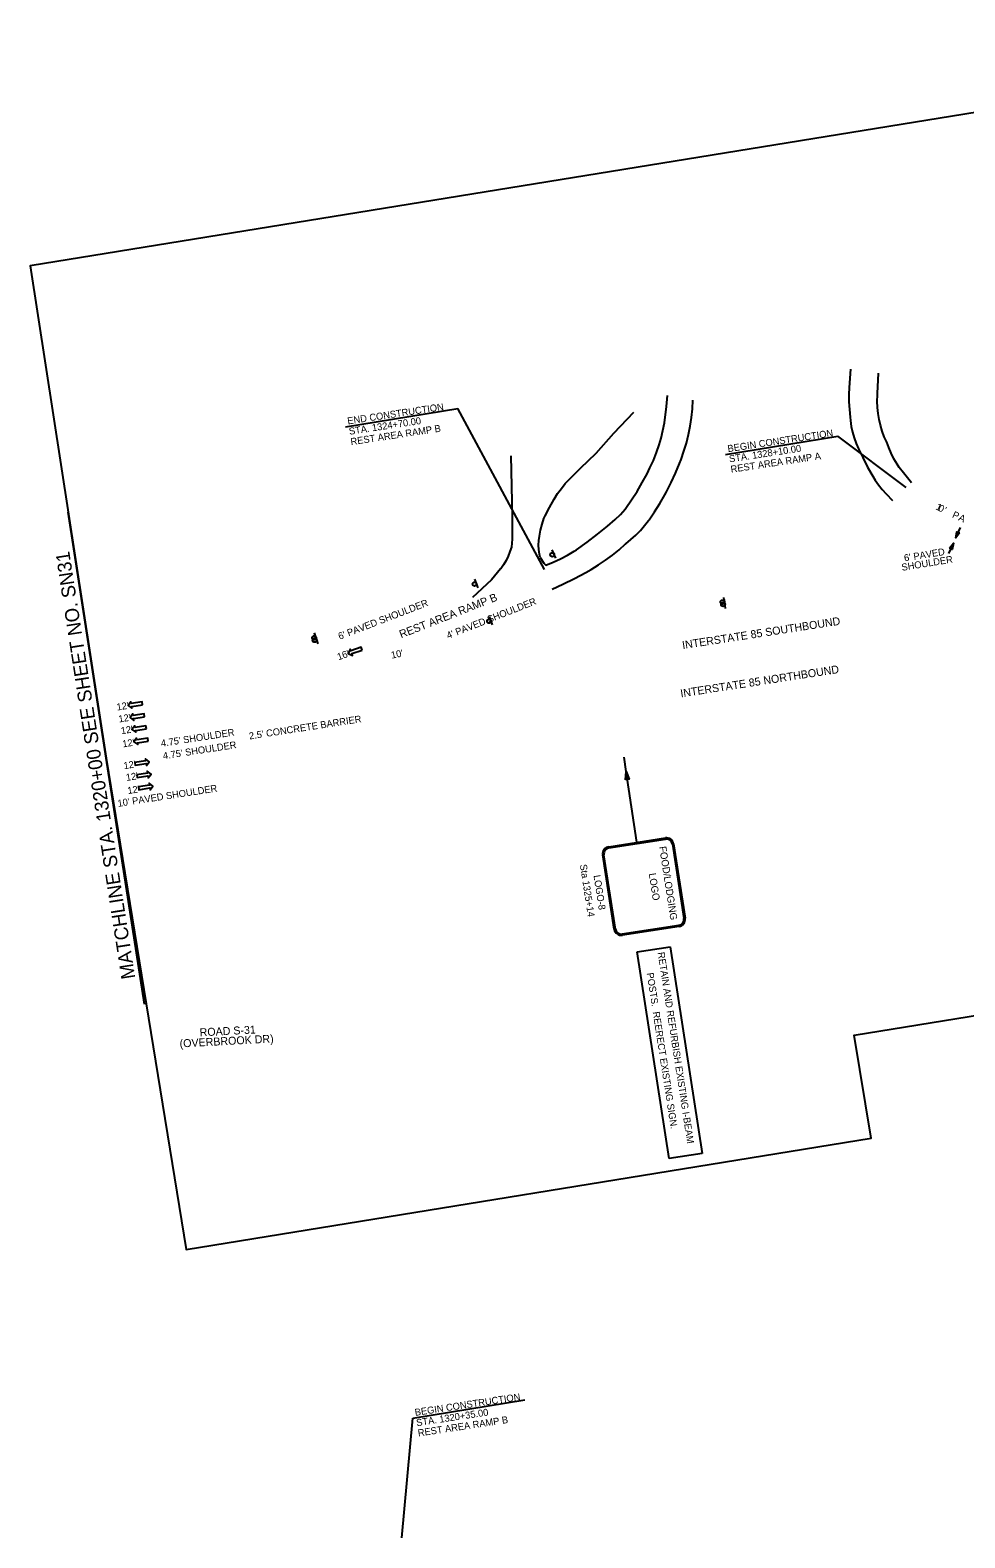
# Model space of a CAD drawing. Extents: x 1781216 to 1782851, y 1180019 to 1181557.
# Drawn here: x 1781216 to 1782155, y 1180019 to 1181533 of the extents above; entities that cross this region are included whole.
import ezdxf

# ---------------------------------------------------------------- set-up
doc = ezdxf.new("R2010")
doc.units = 0
for name, color, linetype in [('RD_EX_Road', 7, 'Continuous'), ('RD_HC_Data', 7, 'Continuous'), ('RD_PD_GR', 7, 'Continuous'), ('RD_PD_PatLn1', 7, 'Continuous'), ('RD_QTY_GR', 7, 'Continuous'), ('RD_SHT_MatchLine', 7, 'Continuous'), ('RD_Sketch2', 7, 'Continuous'), ('RD_TX_RoadID', 7, 'Continuous')]:
    doc.layers.add(name, color=color, linetype=linetype)

# ---------------------------------------------------------------- blocks, each defined once
blk = doc.blocks.new('SARRW2')
at = {"layer": 'RD_Sketch2'}
blk.add_lwpolyline([(-12, 1.2), (-12, -1.2), (-2.8, -1.2), (-2.8, -2.8), (0, 0), (-2.8, 2.8), (-2.8, 1.2)], close=True, dxfattribs=at)
blk = doc.blocks.new('AH')
at = {"layer": 'RD_QTY_GR'}
blk.add_lwpolyline([(-6, 1.5), (0, 0), (-6, -1.5)], close=True, dxfattribs=at)

msp = doc.modelspace()

# ---------------------------------------------------------------- linework, layer by layer
at = {"layer": 'RD_EX_Road'}
for points in [[(1782040, 1181192.4), (1782038.8, 1181174), (1782038.5, 1181167.2), (1782038.5, 1181159.6), (1782038.9, 1181152), (1782039.7, 1181144.5), (1782040, 1181141), (1782040.8, 1181135.1), (1782042, 1181129.3), (1782043.6, 1181123.6), (1782045.6, 1181118), (1782048, 1181112.6), (1782052.3, 1181103.7), (1782057.2, 1181094.2), (1782062.6, 1181085), (1782064.9, 1181081.1), (1782068.2, 1181076.3), (1782071.8, 1181071.8), (1782075.9, 1181067.3), (1782082.4, 1181060.7)], [(1782101.2, 1181078.5), (1782093.2, 1181088.3), (1782089.1, 1181093.9), (1782086.9, 1181097.2), (1782083.7, 1181102.6), (1782080.9, 1181108.2), (1782078.4, 1181114), (1782076.5, 1181119.1), (1782074, 1181124.7), (1782071.9, 1181130.4), (1782070.1, 1181136.2), (1782068.7, 1181142.1), (1782067.8, 1181148.1), (1782067.2, 1181154.2), (1782066.9, 1181160.3), (1782067.1, 1181166.4), (1782067.3, 1181168), (1782068.2, 1181188.7)], [(1781728.2, 1181003.3), (1781732, 1180997.6), (1781734, 1180995.7), (1781741.4, 1180998.7), (1781748.7, 1181002), (1781755.7, 1181005.7), (1781762.6, 1181009.8), (1781765, 1181011.2), (1781775.6, 1181018.9), (1781785.9, 1181026.8), (1781796, 1181035), (1781803.8, 1181041.7), (1781808.9, 1181046.7), (1781813.6, 1181051.9), (1781814.4, 1181052.9), (1781820.2, 1181061.3), (1781825.7, 1181069.8), (1781830.9, 1181078.6), (1781835.7, 1181087.6), (1781838.6, 1181093.4), (1781842.1, 1181101), (1781845.2, 1181108.8), (1781848, 1181116.7), (1781850, 1181123.4), (1781853.1, 1181138.7), (1781855.2, 1181154.9), (1781856.4, 1181166.2)], [(1781740.4, 1180971.5), (1781751.2, 1180976.5), (1781762.8, 1180982.3), (1781774.3, 1180988.4), (1781779.7, 1180991.4), (1781787, 1180995.9), (1781794.1, 1181000.7), (1781800.9, 1181005.8), (1781807.6, 1181011.2), (1781813.9, 1181017), (1781814.4, 1181017.3), (1781819.5, 1181021.4), (1781824.4, 1181025.8), (1781829, 1181030.4), (1781833.3, 1181035.4), (1781837.3, 1181040.5), (1781837.8, 1181041.2), (1781843.3, 1181049.3), (1781848.6, 1181057.6), (1781853.5, 1181066.2), (1781855.3, 1181069.4), (1781860, 1181078.7), (1781864.3, 1181088.1), (1781868.3, 1181097.7), (1781869.9, 1181101.9), (1781872.7, 1181110.1), (1781875.2, 1181118.4), (1781877.2, 1181126.9), (1781878.9, 1181135.4), (1781880.2, 1181144), (1781881.2, 1181152.7), (1781881.7, 1181161.4)], [(1781728.2, 1181003.3), (1781727.5, 1181006.7), (1781726.9, 1181011.3), (1781726.8, 1181015.9), (1781727, 1181020.5), (1781727.6, 1181024.9), (1781728.7, 1181030.9), (1781730.2, 1181036.8), (1781732.1, 1181042.5), (1781733.2, 1181045.3), (1781737.6, 1181053.7), (1781742.4, 1181062), (1781745.9, 1181067.6), (1781749.6, 1181072.7), (1781753.6, 1181077.6), (1781754.5, 1181078.6), (1781768.8, 1181093.3), (1781784.5, 1181108.2), (1781802.5, 1181128.3), (1781822.4, 1181149.5)], [(1781699, 1181105.4), (1781700.3, 1181044.4), (1781700.3, 1181021.9), (1781699.4, 1181013.9), (1781698, 1181009.3), (1781696.3, 1181004.7), (1781694.1, 1181000.3), (1781691.6, 1180996.1), (1781688.8, 1180992.1), (1781688.6, 1180991.9), (1781679.3, 1180981.1), (1781660.4, 1180963.3)]]:
    msp.add_lwpolyline(points, dxfattribs=at)
at = {"layer": 'RD_HC_Data'}
msp.add_lwpolyline([(1782773.7, 1181039.1), (1782674.9, 1181533), (1782674.9, 1181533), (1781216, 1181296.2), (1781292.5, 1180802), (1781372.6, 1180308.5), (1782060.7, 1180420.2), (1782043.9, 1180523.8), (1782850.5, 1180654.8)], close=True, dxfattribs=at)
at = {"layer": 'RD_PD_GR'}
for p, q in [((1781532.7, 1181134.8), (1781645.5, 1181153.1)), ((1781732.6, 1180991.5), (1781645.5, 1181153.1)), ((1781914.5, 1181107), (1782027.3, 1181125.3)), ((1782096.1, 1181073.7), (1782027.3, 1181125.3)), ((1782145.8, 1181023.2), (1782150.4, 1181033.7)), ((1782143.4, 1181017.7), (1782138.6, 1181007.3)), ((1781600.3, 1180139.2), (1781713.1, 1180157.5)), ((1781589.3, 1180019), (1781600.3, 1180139.2))]:
    msp.add_line(p, q, dxfattribs=at)
at = {"layer": 'RD_PD_PatLn1'}
for p, q in [((1781744.1, 1181002.9), (1781740.5, 1181011.2)), ((1781665.9, 1180973.1), (1781662.7, 1180981.6)), ((1781914, 1180954.5), (1781912.9, 1180963.4)), ((1781914.6, 1180952.1), (1781913.4, 1180961.1)), ((1781680.4, 1180935.9), (1781677.3, 1180944.3)), ((1781504.7, 1180919.2), (1781501.7, 1180927.6)), ((1781504.8, 1180919.2), (1781501.8, 1180927.7)), ((1781505.2, 1180916.7), (1781502.2, 1180925.2)), ((1781814.6, 1180788.5), (1781812.8, 1180802.9)), ((1781825.6, 1180717.4), (1781814.6, 1180788.5)), ((1781825.7, 1180607.3), (1781858.9, 1180612.5)), ((1781857.8, 1180399.8), (1781825.7, 1180607.3)), ((1781858.9, 1180612.5), (1781891, 1180404.9)), ((1781891, 1180404.9), (1781857.8, 1180399.8))]:
    msp.add_line(p, q, dxfattribs=at)
msp.add_lwpolyline([(1781813.9, 1180780.1), (1781814.6, 1180788.5), (1781817.9, 1180780.7)], close=True, dxfattribs=at)
for points in [[(1781797.2, 1180713), (1781854.1, 1180721.8)], [(1781797.4, 1180711.8), (1781854.3, 1180720.6)], [(1781861.1, 1180715.6), (1781872.7, 1180640.9)], [(1781862.3, 1180715.8), (1781873.9, 1180641.1)], [(1781802.7, 1180630.1), (1781791.2, 1180704.8)], [(1781803.9, 1180630.2), (1781792.4, 1180705)], [(1781867.7, 1180634), (1781810.8, 1180625.2)], [(1781867.9, 1180632.9), (1781811, 1180624.1)]]:
    msp.add_lwpolyline(points, dxfattribs=at)
for centre in [(1781740.5, 1181006.2), (1781662.4, 1180976.7), (1781911.4, 1180958.7), (1781912, 1180956.3), (1781677, 1180939.4), (1781501.3, 1180922.7), (1781501.4, 1180922.8), (1781501.8, 1180920.3)]:
    msp.add_circle(centre, 2, dxfattribs=at)
for centre, radius, start, end in [((1781798.3, 1180705.9), 7.2, 98.8, 188.8), ((1781798.3, 1180705.9), 6, 98.8, 188.8), ((1781855.2, 1180714.7), 7.2, 8.8, 98.8), ((1781855.2, 1180714.7), 6, 8.8, 98.8), ((1781866.8, 1180640), 6, 278.8, 8.8), ((1781866.8, 1180640), 7.2, 278.8, 8.8), ((1781809.9, 1180631.2), 7.2, 188.8, 278.8), ((1781809.9, 1180631.2), 6, 188.8, 278.8)]:
    msp.add_arc(centre, radius, start, end, dxfattribs=at)
at = {"layer": 'RD_SHT_MatchLine'}
msp.add_lwpolyline([(1781330.8, 1180555), (1781292.5, 1180802), (1781254.3, 1181049.1)], dxfattribs=at)

# ---------------------------------------------------------------- block references
at = {"layer": 'RD_PD_GR'}
for p, rotation in [((1782145.8, 1181023.2), -113.72424217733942), ((1782143.4, 1181017.7), 65.52490361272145)]:
    msp.add_blockref('AH', p, dxfattribs=dict(at, rotation=rotation))
at = {"layer": 'RD_Sketch2', "xscale": 1.2}
for p, yscale, rotation in [((1781535.5, 1180907.1), 1.2000000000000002, -160.6106069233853), ((1781314.5, 1180854.8), 1.2, -171.19998882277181), ((1781316.4, 1180842.7), 1.2, -171.19998882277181), ((1781318.3, 1180830.7), 1.2, -171.19998882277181), ((1781320.2, 1180818.3), 1.2, -171.19998882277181), ((1781335.6, 1180798.4), 1.1999999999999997, 8.800011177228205), ((1781337.5, 1180786), 1.1999999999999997, 8.800011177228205), ((1781339.3, 1180773.9), 1.1999999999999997, 8.800011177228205)]:
    msp.add_blockref('SARRW2', p, dxfattribs=dict(at, yscale=yscale, rotation=rotation))

# ---------------------------------------------------------------- texts
at = {"layer": 'RD_PD_GR'}
for s, rotation, p in [('END CONSTRUCTION', 8.5932, (1781535.2, 1181137)), ('STA. 1324+70.00', 8.5932, (1781536.8, 1181126.6)), ('REST AREA RAMP B', 8.5932, (1781538.4, 1181116.2)), ('BEGIN CONSTRUCTION', 8.5932, (1781917.1, 1181109.2)), ('STA. 1328+10.00', 8.5932, (1781918.6, 1181098.9)), ('REST AREA RAMP A', 8.5932, (1781920.2, 1181088.5)), ('1', 333.188, (1782125, 1181052.1)), ('0', 333.188, (1782127.5, 1181050.8)), ("'", 333.5357, (1782132.7, 1181048.2)), ('P', 335.3085, (1782141.6, 1181043.9)), ('A', 336.5443, (1782147.9, 1181041)), ('SHOULDER', 9.2332, (1782091.9, 1180990)), ("6' PAVED", 9.2332, (1782094.4, 1180999.4)), ("6' PAVED SHOULDER", 21.0743, (1781527, 1180920.7)), ("4' PAVED SHOULDER", 21.5777, (1781635.9, 1180921.5)), ("16'", 19.3894, (1781525.8, 1180900.1)), ("10'", 11.7844, (1781579.3, 1180901.8)), ("12'", 8.8, (1781303.4, 1180849.7)), ("12'", 8.8, (1781305.3, 1180837.7)), ("12'", 8.8, (1781307.7, 1180825.9)), ("2.5' CONCRETE BARRIER", 8.8, (1781436.4, 1180820.6)), ("12'", 8.8, (1781309.2, 1180812.7)), ("4.75' SHOULDER", 8.8, (1781347.9, 1180813.3)), ("4.75' SHOULDER", 8.8, (1781349.9, 1180800.7)), ("12'", 8.8, (1781310.4, 1180790.8)), ("12'", 8.8, (1781312.8, 1180779)), ("10' PAVED SHOULDER", 8.8, (1781304.4, 1180753)), ("12'", 8.8, (1781314.3, 1180765.8)), ('BEGIN CONSTRUCTION', 8.5932, (1781602.9, 1180141.4)), ('STA. 1320+35.00', 8.5932, (1781604.4, 1180131)), ('REST AREA RAMP B', 8.5932, (1781606, 1180120.7))]:
    msp.add_text(s, height=7, rotation=rotation, dxfattribs=at).set_placement(p)
at = {"layer": 'RD_PD_PatLn1'}
for s, height, rotation, p in [('FOOD/LODGING', 7.2, 278.8, (1781847.8, 1180712.9)), ('Sta 1325+14', 7, 278.8001, (1781768.2, 1180694.8)), ('LOGO-8', 7, 278.8001, (1781781.9, 1180684.1)), ('LOGO', 7.2, 278.8, (1781837.4, 1180686)), ('RETAIN AND REFURBISH EXISTING I-BEAM', 7, 278.8001, (1781846.3, 1180606.7)), ('POSTS.  REERECT EXISTING SIGN.', 7, 278.8001, (1781835.3, 1180586))]:
    msp.add_text(s, height=height, rotation=rotation, dxfattribs=at).set_placement(p)
at = {"layer": 'RD_SHT_MatchLine'}
msp.add_text('MATCHLINE STA. 1320+00 SEE SHEET NO. SN31', height=14, rotation=98.8, dxfattribs=at).set_placement((1781321.7, 1180581.1))
at = {"layer": 'RD_TX_RoadID'}
for s, rotation, p in [('REST AREA RAMP B', 21.4224, (1781588.7, 1180922.2)), ('INTERSTATE 85 SOUTHBOUND', 8.8, (1781871.6, 1180911.4)), ('INTERSTATE 85 NORTHBOUND', 8.8, (1781869.8, 1180862.9)), ('ROAD S-31', 3.0316, (1781386.5, 1180522.5)), ('(OVERBROOK DR)', 3.0316, (1781366.4, 1180511.4))]:
    msp.add_text(s, height=8, rotation=rotation, dxfattribs=at).set_placement(p)

doc.saveas('drawing.dxf')
